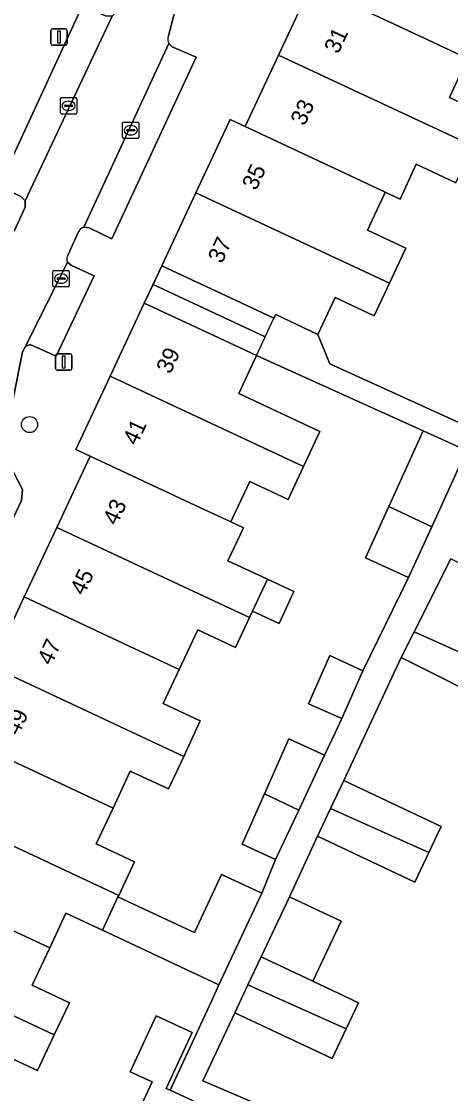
# Model space of a CAD drawing. Extents: x 159817 to 160765, y 380688 to 381638.
# Drawn here: x 160215.2 to 160241.3, y 381322.6 to 381387.8 of the extents above; entities that cross this region are included whole.
import ezdxf

# ---------------------------------------------------------------- set-up
doc = ezdxf.new("R2010")
doc.units = 0
for name, color, linetype in [('IMGEO_Boom', 7, 'Continuous'), ('IMGEO_Erf', 7, 'Continuous'), ('IMGEO_Kolk', 7, 'Continuous'), ('IMGEO_Lichtmast', 7, 'Continuous'), ('IMGEO_Pand', 7, 'Continuous'), ('IMGEO_Pand_nummerreeks', 7, 'Continuous'), ('IMGEO_Pand_overbouw', 7, 'Continuous'), ('IMGEO_Parkeervlak_open', 7, 'Continuous'), ('IMGEO_Rijbaan_lokaal_open', 7, 'Continuous'), ('IMGEO_Voetpad_halfverhard', 7, 'Continuous'), ('IMGEO_Voetpad_open', 7, 'Continuous')]:
    doc.layers.add(name, color=color, linetype=linetype)

msp = doc.modelspace()

# ---------------------------------------------------------------- linework, layer by layer
at = {"layer": 'IMGEO_Boom'}
msp.add_circle((160215.674, 381363.289), 0.489, dxfattribs=at)
at = {"layer": 'IMGEO_Erf'}
for points in [[(160242.315, 381385.568), (160241.203, 381383.19), (160243.512, 381382.109)], [(160241.592, 381378.006), (160239.195, 381379.127), (160238.203, 381377.008), (160237.306, 381377.428), (160237.238, 381377.284), (160236.223, 381375.116), (160238.559, 381374.023), (160237.562, 381371.892), (160236.635, 381369.912), (160234.264, 381371.022), (160233.214, 381368.778), (160233.937, 381366.978), (160242.892, 381362.918)], [(160244.293, 381346.096), (160238.282, 381349.121), (160234.78, 381341.64), (160240.703, 381338.849), (160239.957, 381337.266), (160239.103, 381335.453), (160233.179, 381338.244), (160231.475, 381334.559), (160234.626, 381333.074), (160232.904, 381329.421), (160235.677, 381328.114), (160234.931, 381326.531), (160234.077, 381324.718), (160228.154, 381327.509), (160226.205, 381323.374), (160250.095, 381313.134)], [(160221.551, 381319.898), (160223.126, 381323.297), (160221.799, 381323.908), (160223.382, 381327.324), (160225.567, 381326.311), (160223.986, 381322.901), (160224.219, 381322.793), (160226.75, 381328.25), (160227.194, 381329.201), (160220.101, 381332.522), (160217.888, 381333.558), (160216.902, 381331.452), (160215.838, 381329.177), (160218.095, 381328.121), (160217.18, 381326.166), (160216.161, 381323.99), (160213.937, 381325.03), (160212.924, 381322.868), (160210.219, 381324.135), (160209.096, 381321.736)]]:
    msp.add_lwpolyline(points, dxfattribs=at)
msp.add_lwpolyline([(160233.929, 381349.25), (160235.942, 381348.308), (160238.727, 381353.98), (160236.096, 381355.175), (160237.517, 381358.299), (160239.61, 381362.906), (160229.479, 381367.494), (160228.393, 381365.175), (160233.323, 381362.867), (160232.325, 381360.734), (160231.392, 381358.741), (160229.062, 381359.831), (160228.016, 381357.594), (160227.909, 381357.365), (160228.678, 381357.005), (160227.741, 381355.003), (160230.136, 381353.883), (160231.753, 381353.127), (160230.844, 381351.184), (160229.227, 381351.94), (160229.043, 381351.547), (160228.195, 381349.735), (160225.898, 381350.81), (160224.767, 381348.392), (160223.798, 381346.321), (160226.059, 381345.264), (160225.048, 381343.105), (160224.122, 381341.126), (160221.803, 381342.211), (160220.75, 381339.962), (160219.732, 381337.787), (160222.055, 381336.699), (160221.094, 381334.645), (160221.051, 381334.554), (160225.254, 381332.592), (160225.701, 381332.383), (160227.355, 381335.927), (160229.8, 381334.786), (160230.551, 381336.632), (160230.641, 381336.825), (160228.611, 381337.773), (160229.956, 381340.817), (160231.442, 381344.177), (160233.602, 381343.169), (160234.29, 381344.571), (160234.661, 381345.41), (160232.629, 381346.309)], close=True, dxfattribs=at)
at = {"layer": 'IMGEO_Kolk'}
for p, q in [((160217.548, 381382.259), (160217.548, 381383.111)), ((160217.623, 381383.185), (160218.475, 381383.185)), ((160218.549, 381383.111), (160218.549, 381382.259)), ((160217.807, 381382.679), (160217.807, 381382.691)), ((160218.245, 381382.642), (160217.847, 381382.642)), ((160217.85, 381382.728), (160218.248, 381382.728)), ((160218.059, 381382.405), (160218.034, 381382.405)), ((160218.036, 381382.965), (160218.061, 381382.965)), ((160218.291, 381382.691), (160218.291, 381382.679)), ((160218.475, 381382.185), (160217.623, 381382.185)), ((160221.327, 381380.772), (160221.327, 381381.624)), ((160221.402, 381381.698), (160222.254, 381381.698)), ((160221.586, 381381.192), (160221.586, 381381.204)), ((160222.024, 381381.155), (160221.626, 381381.155)), ((160221.629, 381381.241), (160222.027, 381381.241)), ((160221.815, 381381.478), (160221.84, 381381.478)), ((160222.07, 381381.204), (160222.07, 381381.192)), ((160222.328, 381381.624), (160222.328, 381380.772)), ((160222.254, 381380.698), (160221.402, 381380.698)), ((160221.838, 381380.918), (160221.813, 381380.918)), ((160217.091, 381371.747), (160217.091, 381372.599)), ((160217.166, 381372.673), (160218.018, 381372.673)), ((160218.092, 381372.599), (160218.092, 381371.747)), ((160217.35, 381372.167), (160217.35, 381372.179)), ((160217.788, 381372.13), (160217.39, 381372.13)), ((160217.393, 381372.216), (160217.791, 381372.216)), ((160217.579, 381372.453), (160217.604, 381372.453)), ((160217.834, 381372.179), (160217.834, 381372.167)), ((160218.018, 381371.673), (160217.166, 381371.673)), ((160217.602, 381371.893), (160217.577, 381371.893))]:
    msp.add_line(p, q, dxfattribs=at)
for points in [[(160217.548, 381382.259), (160217.548, 381383.111)], [(160217.623, 381383.185), (160218.475, 381383.185)], [(160218.549, 381383.111), (160218.549, 381382.259)], [(160218.475, 381382.185), (160217.623, 381382.185)], [(160221.327, 381380.772), (160221.327, 381381.624)], [(160221.402, 381381.698), (160222.254, 381381.698)], [(160222.328, 381381.624), (160222.328, 381380.772)], [(160222.254, 381380.698), (160221.402, 381380.698)], [(160217.091, 381371.747), (160217.091, 381372.599)], [(160217.166, 381372.673), (160218.018, 381372.673)], [(160218.092, 381372.599), (160218.092, 381371.747)], [(160218.018, 381371.673), (160217.166, 381371.673)]]:
    msp.add_lwpolyline(points, dxfattribs=at)
for centre, radius, start, end in [((160217.625, 381383.109), 0.0765, 91.55205, 178.44795), ((160217.625, 381383.109), 0.0765, 91.55205, 178.44795), ((160218.473, 381383.109), 0.0765, 1.55205, 88.44795), ((160218.473, 381383.109), 0.0765, 1.55205, 88.44795), ((160217.847, 381382.688), 0.0403, 85.87752, 175.75265), ((160217.844, 381382.678), 0.0366, 178.93798, 274.71019), ((160218.248, 381382.685), 0.043, 264.86636, 352.45326), ((160218.252, 381382.69), 0.0386, 1.73085, 96.63898), ((160217.625, 381382.261), 0.0765, 181.55205, 268.44795), ((160217.625, 381382.261), 0.0765, 181.55205, 268.44795), ((160218.473, 381382.261), 0.0765, 271.55205, 358.44795), ((160218.473, 381382.261), 0.0765, 271.55205, 358.44795), ((160221.404, 381381.622), 0.0765, 91.55205, 178.44795), ((160221.404, 381381.622), 0.0765, 91.55205, 178.44795), ((160221.626, 381381.201), 0.0403, 85.87752, 175.75265), ((160221.623, 381381.191), 0.0366, 178.93798, 274.71019), ((160222.027, 381381.198), 0.043, 264.86636, 352.45326), ((160222.031, 381381.203), 0.0386, 1.73085, 96.63898), ((160222.252, 381381.622), 0.0765, 1.55205, 88.44795), ((160222.252, 381381.622), 0.0765, 1.55205, 88.44795), ((160221.404, 381380.774), 0.0765, 181.55205, 268.44795), ((160221.404, 381380.774), 0.0765, 181.55205, 268.44795), ((160222.252, 381380.774), 0.0765, 271.55205, 358.44795), ((160222.252, 381380.774), 0.0765, 271.55205, 358.44795), ((160217.168, 381372.597), 0.0765, 91.55205, 178.44795), ((160217.168, 381372.597), 0.0765, 91.55205, 178.44795), ((160218.016, 381372.597), 0.0765, 1.55205, 88.44795), ((160218.016, 381372.597), 0.0765, 1.55205, 88.44795), ((160217.39, 381372.176), 0.0403, 85.87752, 175.75265), ((160217.387, 381372.166), 0.0366, 178.93798, 274.71019), ((160217.791, 381372.173), 0.043, 264.86636, 352.45326), ((160217.795, 381372.178), 0.0386, 1.73085, 96.63898), ((160217.168, 381371.749), 0.0765, 181.55205, 268.44795), ((160217.168, 381371.749), 0.0765, 181.55205, 268.44795), ((160218.016, 381371.749), 0.0765, 271.55205, 358.44795), ((160218.016, 381371.749), 0.0765, 271.55205, 358.44795)]:
    msp.add_arc(centre, radius, start, end, dxfattribs=at)
for centre, major_axis, ratio, start_param, end_param in [((160218.035, 381382.685), (-0.387, 0.002), 0.722429, 4.712389, 7.853982), ((160218.06, 381382.685), (-0.39, 0.002), 0.717154, 1.570796, 4.712389), ((160221.814, 381381.198), (-0.387, 0.002), 0.722429, 4.712389, 7.853982), ((160221.839, 381381.198), (-0.39, 0.002), 0.717154, 1.570796, 4.712389), ((160217.578, 381372.173), (-0.387, 0.002), 0.722429, 4.712389, 7.853982), ((160217.603, 381372.173), (-0.39, 0.002), 0.717154, 1.570796, 4.712389)]:
    msp.add_ellipse(centre, major_axis=major_axis, ratio=ratio, start_param=start_param, end_param=end_param, dxfattribs=at)
at = {"layer": 'IMGEO_Lichtmast'}
for p, q in [((160216.968, 381386.474), (160216.968, 381387.274)), ((160216.968, 381387.274), (160216.968, 381386.474)), ((160217.068, 381387.374), (160217.858, 381387.374)), ((160217.858, 381387.374), (160217.068, 381387.374)), ((160217.958, 381387.274), (160217.958, 381386.474)), ((160217.958, 381386.474), (160217.958, 381387.274)), ((160217.858, 381386.374), (160217.068, 381386.374)), ((160217.068, 381386.374), (160217.858, 381386.374)), ((160217.255, 381366.7), (160217.255, 381367.5)), ((160217.255, 381367.5), (160217.255, 381366.7)), ((160217.355, 381367.6), (160218.145, 381367.6)), ((160218.145, 381367.6), (160217.355, 381367.6)), ((160218.245, 381367.5), (160218.245, 381366.7)), ((160218.245, 381366.7), (160218.245, 381367.5)), ((160218.145, 381366.6), (160217.355, 381366.6)), ((160217.355, 381366.6), (160218.145, 381366.6))]:
    msp.add_line(p, q, dxfattribs=at)
for points in [[(160217.388, 381387.249), (160217.538, 381387.249), (160217.538, 381386.499), (160217.388, 381386.499), (160217.388, 381387.249)], [(160217.675, 381367.475), (160217.825, 381367.475), (160217.825, 381366.725), (160217.675, 381366.725), (160217.675, 381367.475)]]:
    msp.add_lwpolyline(points, dxfattribs=at)
for centre, start, end in [((160217.068, 381387.274), 90, 180), ((160217.068, 381387.274), 90, 180), ((160217.858, 381387.274), 0, 90), ((160217.858, 381387.274), 360, 90), ((160217.068, 381386.474), 180, 270), ((160217.068, 381386.474), 180, 270), ((160217.858, 381386.474), 270, 0), ((160217.858, 381386.474), 270, 0), ((160217.355, 381367.5), 90, 180), ((160217.355, 381367.5), 90, 180), ((160218.145, 381367.5), 0, 90), ((160218.145, 381367.5), 360, 90), ((160217.355, 381366.7), 180, 270), ((160217.355, 381366.7), 180, 270), ((160218.145, 381366.7), 270, 0), ((160218.145, 381366.7), 270, 0)]:
    msp.add_arc(centre, 0.1, start, end, dxfattribs=at)
at = {"layer": 'IMGEO_Pand'}
for points in [[(160242.315, 381385.568), (160243.335, 381387.748), (160245.687, 381386.648), (160246.653, 381388.713), (160246.548, 381388.762), (160234.789, 381394.267), (160232.802, 381390.02), (160239.584, 381386.846)], [(160242.315, 381385.568), (160239.584, 381386.846), (160232.802, 381390.02), (160230.816, 381385.775), (160242.638, 381380.241), (160243.512, 381382.109), (160241.203, 381383.19)], [(160230.816, 381385.775), (160228.778, 381381.421), (160235.539, 381378.255), (160237.306, 381377.428), (160238.203, 381377.008), (160239.195, 381379.127), (160241.592, 381378.006), (160242.638, 381380.241)], [(160235.539, 381378.255), (160228.778, 381381.421), (160227.869, 381381.844), (160225.791, 381377.397), (160237.562, 381371.892), (160238.559, 381374.023), (160236.223, 381375.116), (160237.238, 381377.284), (160237.306, 381377.428)], [(160237.562, 381371.892), (160225.791, 381377.397), (160223.712, 381372.948), (160228.242, 381370.831), (160230.539, 381369.758), (160230.643, 381369.981), (160233.214, 381368.778), (160234.264, 381371.022), (160236.635, 381369.912)], [(160220.571, 381366.228), (160232.325, 381360.734), (160233.323, 381362.867), (160228.393, 381365.175), (160229.479, 381367.494), (160227.184, 381368.566), (160222.653, 381370.683)], [(160232.325, 381360.734), (160220.571, 381366.228), (160218.489, 381361.773), (160219.354, 381361.369), (160226.078, 381358.222), (160227.909, 381357.365), (160228.016, 381357.594), (160229.062, 381359.831), (160231.392, 381358.741)], [(160240.135, 381357.076), (160242.241, 381361.71), (160239.61, 381362.906), (160237.517, 381358.299)], [(160227.909, 381357.365), (160226.078, 381358.222), (160219.354, 381361.369), (160217.324, 381357.031), (160229.043, 381351.547), (160229.227, 381351.94), (160230.136, 381353.883), (160227.741, 381355.003), (160228.678, 381357.005)], [(160240.135, 381357.076), (160237.517, 381358.299), (160236.096, 381355.175), (160238.727, 381353.98)], [(160217.324, 381357.031), (160215.345, 381352.802), (160222.04, 381349.668), (160224.767, 381348.392), (160225.898, 381350.81), (160228.195, 381349.735), (160229.043, 381351.547)], [(160245.216, 381347.931), (160247.314, 381352.099), (160241.303, 381355.124), (160239.064, 381350.674)], [(160230.136, 381353.883), (160229.227, 381351.94), (160230.844, 381351.184), (160231.753, 381353.127)], [(160213.366, 381348.573), (160225.048, 381343.105), (160226.059, 381345.264), (160223.798, 381346.321), (160224.767, 381348.392), (160222.04, 381349.668), (160215.345, 381352.802)], [(160245.216, 381347.931), (160239.064, 381350.674), (160238.282, 381349.121), (160244.293, 381346.096)], [(160235.942, 381348.308), (160233.929, 381349.25), (160232.629, 381346.309), (160234.661, 381345.41)], [(160211.387, 381344.343), (160218.164, 381341.172), (160220.75, 381339.962), (160221.803, 381342.211), (160224.122, 381341.126), (160225.048, 381343.105), (160213.366, 381348.573)], [(160211.387, 381344.343), (160209.408, 381340.114), (160221.094, 381334.645), (160222.055, 381336.699), (160219.732, 381337.787), (160220.75, 381339.962), (160218.164, 381341.172)], [(160233.602, 381343.169), (160231.442, 381344.177), (160229.956, 381340.817), (160232.047, 381339.838)], [(160233.975, 381339.933), (160239.957, 381337.266), (160240.703, 381338.849), (160234.78, 381341.64)], [(160232.047, 381339.838), (160229.956, 381340.817), (160228.611, 381337.773), (160230.641, 381336.825)], [(160209.408, 381340.114), (160207.429, 381335.885), (160214.254, 381332.691), (160216.902, 381331.452), (160217.888, 381333.558), (160220.101, 381332.522), (160221.051, 381334.554), (160221.094, 381334.645)], [(160233.975, 381339.933), (160233.179, 381338.244), (160239.103, 381335.453), (160239.957, 381337.266)], [(160217.18, 381326.166), (160218.095, 381328.121), (160215.838, 381329.177), (160216.902, 381331.452), (160214.254, 381332.691), (160207.429, 381335.885), (160205.45, 381331.655)], [(160229.8, 381334.786), (160227.355, 381335.927), (160225.701, 381332.383), (160225.254, 381332.592), (160221.051, 381334.554), (160220.101, 381332.522), (160227.194, 381329.201)], [(160231.475, 381334.559), (160229.754, 381330.905), (160232.904, 381329.421), (160234.626, 381333.074)], [(160205.45, 381331.655), (160203.421, 381327.319), (160210.219, 381324.135), (160212.924, 381322.868), (160213.937, 381325.03), (160216.161, 381323.99), (160217.18, 381326.166)], [(160232.904, 381329.421), (160229.754, 381330.905), (160228.95, 381329.198), (160234.931, 381326.531), (160235.677, 381328.114)], [(160228.95, 381329.198), (160228.154, 381327.509), (160234.077, 381324.718), (160234.931, 381326.531)], [(160225.567, 381326.311), (160223.382, 381327.324), (160221.799, 381323.908), (160223.126, 381323.297), (160221.551, 381319.898), (160222.421, 381319.495), (160223.762, 381318.873), (160224.027, 381318.75), (160225.471, 381321.826), (160225.62, 381322.143), (160224.219, 381322.793), (160223.986, 381322.901)]]:
    msp.add_lwpolyline(points, close=True, dxfattribs=at)
at = {"layer": 'IMGEO_Pand_overbouw'}
for points in [[(160230.539, 381369.758), (160228.242, 381370.831), (160223.712, 381372.948), (160223.183, 381371.816), (160230.009, 381368.626)], [(160222.653, 381370.683), (160227.184, 381368.566), (160229.479, 381367.494), (160230.009, 381368.626), (160223.183, 381371.816)]]:
    msp.add_lwpolyline(points, close=True, dxfattribs=at)
at = {"layer": 'IMGEO_Parkeervlak_open'}
for points in [[(160220.289, 381388.152), (160218.892, 381388.787), (160213.806, 381377.796), (160215.148, 381377.161), (160215.407, 381376.905), (160220.689, 381388.147)], [(160224.348, 381386.265), (160224.142, 381386.468), (160218.985, 381375.292), (160219.298, 381375.256), (160220.676, 381374.594), (160225.799, 381385.637)], [(160215.719, 381368.156), (160217.295, 381367.451), (160219.594, 381372.342), (160218.222, 381372.975), (160217.985, 381373.181), (160215.421, 381368.045)]]:
    msp.add_lwpolyline(points, close=True, dxfattribs=at)
msp.add_lwpolyline([(160203.252, 381333.315), (160215.185, 381358.665), (160215.252, 381359.334), (160214.09, 381361.566), (160214.068, 381361.802), (160213.839, 381360.932), (160213.284, 381359.351), (160199.639, 381330.369), (160200.708, 381331.706), (160201.048, 381331.963), (160202.829, 381332.847)], dxfattribs=at)
at = {"layer": 'IMGEO_Rijbaan_lokaal_open'}
for points in [[(160220.689, 381388.147), (160215.407, 381376.905)], [(160224.134, 381386.932), (160224.442, 381388.208)], [(160218.985, 381375.292), (160224.142, 381386.468)], [(160215.403, 381376.51), (160214.768, 381375.103)], [(160215.407, 381376.905), (160215.403, 381376.51)], [(160218.024, 381373.638), (160218.643, 381375.016)], [(160215.421, 381368.045), (160217.985, 381373.181)], [(160215.246, 381367.718), (160215.421, 381368.045)], [(160214.068, 381361.802), (160215.246, 381367.718)]]:
    msp.add_lwpolyline(points, dxfattribs=at)
for centre, radius, start, end in [((160224.582, 381386.708), 0.501, 153.38048, 208.59504), ((160219.094, 381374.807), 0.497, 102.6597, 155.14857), ((160218.364, 381373.379), 0.427, 142.67609, 207.5684)]:
    msp.add_arc(centre, radius, start, end, dxfattribs=at)
at = {"layer": 'IMGEO_Voetpad_halfverhard'}
for points in [[(160242.892, 381362.918), (160233.937, 381366.978), (160233.214, 381368.778), (160230.643, 381369.981), (160230.539, 381369.758), (160228.242, 381370.831), (160223.712, 381372.948), (160222.653, 381370.683), (160227.184, 381368.566), (160229.479, 381367.494), (160239.61, 381362.906), (160242.241, 381361.71), (160240.135, 381357.076), (160238.727, 381353.98), (160235.942, 381348.308), (160234.661, 381345.41), (160234.29, 381344.571), (160233.602, 381343.169), (160232.047, 381339.838), (160230.641, 381336.825), (160230.551, 381336.632), (160229.8, 381334.786), (160227.194, 381329.201), (160226.75, 381328.25), (160224.219, 381322.793), (160225.62, 381322.143)], [(160250.095, 381313.134), (160226.205, 381323.374), (160228.154, 381327.509), (160228.95, 381329.198), (160229.754, 381330.905), (160231.475, 381334.559), (160233.179, 381338.244), (160233.975, 381339.933), (160234.78, 381341.64), (160238.282, 381349.121), (160239.064, 381350.674), (160241.303, 381355.124)]]:
    msp.add_lwpolyline(points, dxfattribs=at)
at = {"layer": 'IMGEO_Voetpad_open'}
for points in [[(160225.791, 381377.397), (160227.869, 381381.844), (160228.778, 381381.421), (160230.816, 381385.775), (160232.802, 381390.02), (160234.789, 381394.267), (160236.776, 381398.512), (160238.763, 381402.758), (160240.749, 381407.004), (160242.736, 381411.249), (160244.774, 381415.604), (160242.092, 381416.859), (160244.164, 381421.287)], [(160227.243, 381396.192), (160225.974, 381393.449), (160225.232, 381391.529), (160224.952, 381390.606), (160224.442, 381388.208), (160224.134, 381386.932)], [(160211.032, 381364.48), (160211.979, 381369.41), (160211.952, 381369.689), (160211.724, 381369.947), (160210.405, 381370.544), (160212.728, 381375.521), (160214.084, 381374.875), (160214.463, 381374.849), (160214.768, 381375.103), (160215.403, 381376.51), (160215.407, 381376.905), (160215.148, 381377.161), (160213.806, 381377.796), (160218.892, 381388.787), (160220.289, 381388.152), (160220.689, 381388.147), (160220.949, 381388.406), (160221.021, 381388.541), (160221.187, 381389.146), (160221.471, 381391.895), (160221.49, 381391.998), (160221.48, 381392.411), (160221.395, 381392.774), (160220.765, 381394.688)], [(160224.142, 381386.468), (160224.348, 381386.265), (160225.799, 381385.637), (160220.676, 381374.594), (160219.298, 381375.256), (160218.985, 381375.292)], [(160196.663, 381319.809), (160198.686, 381324.132), (160200.76, 381328.565), (160203.421, 381327.319), (160205.45, 381331.655), (160207.429, 381335.885), (160209.408, 381340.114), (160211.387, 381344.343), (160213.366, 381348.573), (160215.345, 381352.802), (160217.324, 381357.031), (160219.354, 381361.369), (160218.489, 381361.773), (160220.571, 381366.228), (160222.653, 381370.683), (160223.712, 381372.948), (160225.791, 381377.397)], [(160218.643, 381375.016), (160218.024, 381373.638)], [(160217.985, 381373.181), (160218.222, 381372.975), (160219.594, 381372.342), (160217.295, 381367.451), (160215.719, 381368.156), (160215.421, 381368.045), (160215.246, 381367.718), (160214.068, 381361.802), (160214.09, 381361.566), (160215.252, 381359.334), (160215.185, 381358.665), (160203.252, 381333.315)]]:
    msp.add_lwpolyline(points, dxfattribs=at)
for centre, radius, start, end in [((160224.582, 381386.708), 0.501, 153.38048, 208.59504), ((160219.094, 381374.807), 0.497, 102.6597, 155.14857), ((160218.364, 381373.379), 0.427, 142.67609, 207.5684)]:
    msp.add_arc(centre, radius, start, end, dxfattribs=at)

# ---------------------------------------------------------------- texts
at = {"layer": 'IMGEO_Pand_nummerreeks'}
for s, rotation, p in [('31', 64.92258, (160234.445, 381385.793)), ('33', 64.92185, (160232.397, 381381.416)), ('35', 64.95623, (160229.451, 381377.482)), ('37', 64.95385, (160227.373, 381373.035)), ('39', 64.95143, (160224.233, 381366.319)), ('41', 64.9505, (160222.199, 381361.965)), ('43', 64.92185, (160220.979, 381357.102)), ('45', 64.92372, (160218.987, 381352.847)), ('47', 64.92372, (160216.996, 381348.59)), ('49', 64.92372, (160215.004, 381344.334))]:
    msp.add_text(s, height=1, rotation=rotation, dxfattribs=at).set_placement(p)

doc.saveas('drawing.dxf')
